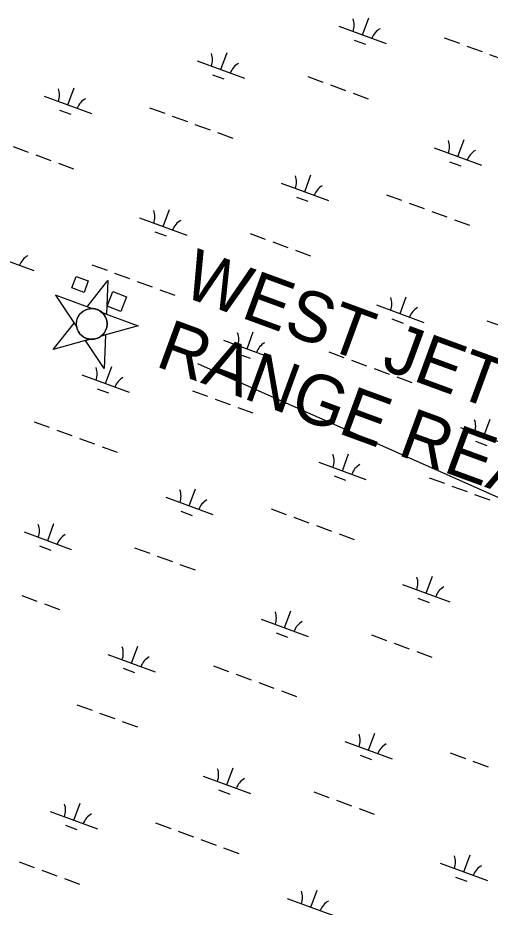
# Model space of a CAD drawing. Extents: x 3972907 to 3994831, y 172639 to 190852.
# Drawn here: x 3980783 to 3981252, y 185019 to 185903 of the extents above; entities that cross this region are included whole.
import ezdxf

# ---------------------------------------------------------------- set-up
doc = ezdxf.new("R2010")
doc.units = 0
for name, color, linetype in [('V-BLDG-OTLN', 7, 'Continuous'), ('V-CHAN-NAID', 7, 'Continuous'), ('V-RIVR-JETY', 7, 'Continuous'), ('V-RIVR-RANG', 7, 'Continuous'), ('V-WETL-SWMP', 7, 'Continuous')]:
    doc.layers.add(name, color=color, linetype=linetype)

msp = doc.modelspace()

# ---------------------------------------------------------------- linework, layer by layer
at = {"layer": 'V-BLDG-OTLN'}
for points in [[(3980848.54, 185630.29), (3980836.36, 185634.69), (3980840.47, 185646.04), (3980852.64, 185641.64)], [(3980871.33, 185616.44), (3980876.94, 185630.99), (3980890.54, 185625.75), (3980884.93, 185611.2)]]:
    msp.add_lwpolyline(points, close=True, dxfattribs=at)
at = {"layer": 'V-CHAN-NAID'}
for points in [[(3980855.84, 185614.14), (3980851.36, 185615.82), (3980872.2, 185641.99), (3980870.72, 185608.57), (3980866.23, 185610.25), (3980865.59, 185610.79), (3980864.71, 185611.44), (3980863.83, 185612.01), (3980862.93, 185612.5), (3980862.4, 185612.75), (3980861.69, 185613.06), (3980860.88, 185613.35), (3980860.23, 185613.56), (3980859.3, 185613.79), (3980858.62, 185613.92), (3980857.72, 185614.05), (3980856.93, 185614.11), (3980856.39, 185614.14)], [(3980855.84, 185614.14), (3980820.03, 185627.56), (3980841.12, 185595.65), (3980840.92, 185596.74), (3980840.82, 185597.64), (3980840.77, 185598.71), (3980840.8, 185599.79), (3980840.86, 185600.48), (3980840.97, 185601.3), (3980841.1, 185602.02), (3980841.29, 185602.8), (3980841.54, 185603.64), (3980841.8, 185604.38), (3980842.21, 185605.34), (3980842.57, 185606.07), (3980843.14, 185607.03), (3980843.69, 185607.85), (3980844.3, 185608.63), (3980844.9, 185609.31), (3980845.51, 185609.93), (3980846.16, 185610.51), (3980846.96, 185611.14), (3980847.69, 185611.66), (3980848.38, 185612.08), (3980849.05, 185612.44), (3980849.89, 185612.85), (3980850.55, 185613.12), (3980851.6, 185613.48), (3980852.32, 185613.68), (3980853.29, 185613.89), (3980854.27, 185614.04), (3980855.07, 185614.11)], [(3980866.23, 185610.25), (3980902.04, 185596.83), (3980865.18, 185586.63), (3980865.86, 185587.18), (3980866.64, 185587.87), (3980867.25, 185588.49), (3980867.93, 185589.29), (3980868.49, 185590.03), (3980868.96, 185590.73), (3980869.48, 185591.61), (3980869.84, 185592.32), (3980870.27, 185593.33), (3980870.62, 185594.31), (3980870.91, 185595.38), (3980871.09, 185596.25), (3980871.24, 185597.38), (3980871.31, 185598.5), (3980871.3, 185599.56), (3980871.24, 185600.35), (3980871.1, 185601.42), (3980870.9, 185602.41), (3980870.62, 185603.42), (3980870.29, 185604.36), (3980869.93, 185605.22), (3980869.43, 185606.22), (3980868.85, 185607.18), (3980868.27, 185608.02), (3980867.58, 185608.88), (3980867.02, 185609.49)], [(3980854.49, 185583.68), (3980817.63, 185573.49), (3980838.47, 185599.65), (3980841.12, 185595.65), (3980841.25, 185595.09), (3980841.58, 185593.98), (3980841.9, 185593.1), (3980842.33, 185592.15), (3980842.77, 185591.32), (3980843.25, 185590.53), (3980843.74, 185589.82), (3980844.35, 185589.05), (3980845, 185588.32), (3980845.7, 185587.64), (3980846.28, 185587.13), (3980846.96, 185586.6), (3980847.9, 185585.95), (3980848.57, 185585.55), (3980849.48, 185585.08), (3980850.18, 185584.77), (3980851.05, 185584.44), (3980851.86, 185584.18), (3980852.69, 185583.97), (3980853.64, 185583.79)], [(3980865.18, 185586.63), (3980869.8, 185587.91), (3980868.31, 185554.49), (3980849.87, 185582.4), (3980854.49, 185583.68), (3980855.36, 185583.61), (3980856.21, 185583.6), (3980857.38, 185583.66), (3980858.35, 185583.77), (3980859.41, 185583.98), (3980860.44, 185584.25), (3980861.38, 185584.56), (3980862.19, 185584.89), (3980863.08, 185585.32), (3980863.89, 185585.77), (3980864.67, 185586.27)]]:
    msp.add_lwpolyline(points, close=True, dxfattribs=at)
msp.add_circle((3980856.04, 185598.87), 15.27, dxfattribs=at)
at = {"layer": 'V-RIVR-JETY'}
msp.add_spline([(3980663.75, 188142.49), (3980923.3, 187897.84), (3981219.12, 187593.73), (3981381.55, 187411.23), (3981548.76, 187223.47), (3981745.95, 186997.4), (3981995.88, 186703.14), (3982287.95, 186350.33), (3982495.82, 186079.54), (3982762.84, 185654.69), (3982971.02, 185292.43), (3983111.24, 185037.47), (3983200.02, 184881.79), (3983229.93, 184826.38)], degree=3, dxfattribs=at)
at = {"layer": 'V-RIVR-RANG'}
msp.add_lwpolyline([(3980961.27, 185559.67), (3981961.68, 185114.26)], dxfattribs=at)
at = {"layer": 'V-WETL-SWMP'}
for p, q in [((3981125.21, 185886.27), (3981131.42, 185903.17)), ((3981101.75, 185894.9), (3981148.68, 185877.65)), ((3981206.52, 185883.42), (3981221.53, 185877.9)), ((3981116.92, 185881.1), (3981128.18, 185876.96)), ((3981229.04, 185875.14), (3981244.06, 185869.62)), ((3980984.44, 185851.79), (3980990.65, 185868.69)), ((3981251.57, 185866.86), (3981266.59, 185861.34)), ((3980960.97, 185860.41), (3981007.9, 185843.17)), ((3980976.14, 185846.62), (3980987.41, 185842.48)), ((3981070.85, 185844.76), (3981085.87, 185839.24)), ((3980832.28, 185816.72), (3980838.49, 185833.62)), ((3981093.38, 185836.48), (3981108.4, 185830.96)), ((3980808.82, 185825.35), (3980855.75, 185808.1)), ((3981115.9, 185828.2), (3981130.92, 185822.68)), ((3980913.58, 185813.87), (3980928.6, 185808.35)), ((3980823.99, 185811.55), (3980835.25, 185807.41)), ((3980936.11, 185805.59), (3980951.13, 185800.07)), ((3980958.64, 185797.31), (3980973.66, 185791.79)), ((3980981.16, 185789.03), (3980996.18, 185783.51)), ((3981219.99, 185765.21), (3981226.2, 185782.11)), ((3980777.92, 185775.21), (3980792.94, 185769.69)), ((3981196.52, 185773.84), (3981243.45, 185756.59)), ((3980800.45, 185766.93), (3980815.46, 185761.41)), ((3981211.69, 185760.04), (3981222.96, 185755.9)), ((3980822.97, 185758.65), (3980837.99, 185753.13)), ((3981067.83, 185730.15), (3981074.04, 185747.04)), ((3981044.36, 185738.77), (3981091.29, 185721.52)), ((3981059.54, 185724.98), (3981070.8, 185720.84)), ((3981149.13, 185727.29), (3981164.15, 185721.77)), ((3981171.66, 185719.02), (3981186.68, 185713.5)), ((3980927.05, 185695.66), (3980933.26, 185712.56)), ((3981194.19, 185710.74), (3981209.2, 185705.22)), ((3980903.59, 185704.29), (3980950.52, 185687.04)), ((3981216.71, 185702.46), (3981231.73, 185696.94)), ((3980918.76, 185690.49), (3980930.02, 185686.35)), ((3981013.47, 185688.64), (3981028.48, 185683.12)), ((3981035.99, 185680.36), (3981051.01, 185674.84)), ((3981058.52, 185672.08), (3981073.54, 185666.56)), ((3980751.43, 185669.22), (3980798.36, 185651.97)), ((3980856.2, 185657.74), (3980871.22, 185652.22)), ((3980878.73, 185649.46), (3980893.74, 185643.94)), ((3980901.25, 185641.19), (3980916.27, 185635.67)), ((3980923.78, 185632.91), (3980938.8, 185627.39)), ((3981139.14, 185617.71), (3981186.07, 185600.46)), ((3981162.6, 185609.09), (3981168.81, 185625.98)), ((3981154.31, 185603.92), (3981165.57, 185599.78)), ((3981249.01, 185602.06), (3981264.03, 185596.54)), ((3981010.44, 185574.02), (3981016.65, 185590.92)), ((3980986.98, 185582.65), (3981033.91, 185565.4)), ((3981002.15, 185568.85), (3981013.41, 185564.71)), ((3981091.75, 185571.17), (3981106.77, 185565.65)), ((3980869.67, 185539.54), (3980875.88, 185556.43)), ((3981114.27, 185562.89), (3981129.29, 185557.37)), ((3980846.21, 185548.16), (3980893.14, 185530.91)), ((3981136.8, 185554.61), (3981151.82, 185549.09)), ((3981159.33, 185546.33), (3981174.35, 185540.81)), ((3980861.38, 185534.37), (3980872.64, 185530.23)), ((3980956.08, 185532.51), (3980971.1, 185526.99)), ((3980978.61, 185524.23), (3980993.63, 185518.71)), ((3981001.14, 185515.95), (3981016.15, 185510.43)), ((3981245.99, 185487.45), (3981252.2, 185504.34)), ((3980798.82, 185501.62), (3980813.83, 185496.1)), ((3981222.53, 185496.07), (3981269.46, 185478.82)), ((3980821.34, 185493.34), (3980836.36, 185487.82)), ((3980843.87, 185485.06), (3980858.89, 185479.54)), ((3980866.4, 185476.78), (3980881.41, 185471.26)), ((3981237.7, 185482.27), (3981248.96, 185478.13)), ((3981105.22, 185452.96), (3981111.43, 185469.86)), ((3981081.75, 185461.59), (3981128.68, 185444.34)), ((3981096.92, 185447.79), (3981108.19, 185443.65)), ((3981191.63, 185445.94), (3981206.65, 185440.42)), ((3980953.06, 185417.9), (3980959.27, 185434.79)), ((3981214.16, 185437.66), (3981229.17, 185432.14)), ((3980929.6, 185426.52), (3980976.53, 185409.27)), ((3981236.68, 185429.38), (3981251.7, 185423.86)), ((3981034.36, 185415.04), (3981049.38, 185409.52)), ((3980944.77, 185412.72), (3980956.03, 185408.58)), ((3981056.89, 185406.76), (3981071.91, 185401.24)), ((3980812.29, 185383.41), (3980818.5, 185400.31)), ((3981079.42, 185398.48), (3981094.43, 185392.96)), ((3980788.82, 185392.04), (3980835.75, 185374.79)), ((3981101.94, 185390.2), (3981116.96, 185384.68)), ((3980803.99, 185378.24), (3980815.26, 185374.1)), ((3980898.7, 185376.39), (3980913.72, 185370.87)), ((3980921.23, 185368.11), (3980936.24, 185362.59)), ((3980943.75, 185359.83), (3980958.77, 185354.31)), ((3981188.61, 185331.32), (3981194.82, 185348.22)), ((3981165.14, 185339.94), (3981212.07, 185322.7)), ((3980786.49, 185328.93), (3980801.5, 185323.41)), ((3981180.31, 185326.15), (3981191.58, 185322.01)), ((3980809.01, 185320.65), (3980824.03, 185315.13)), ((3981047.83, 185296.84), (3981054.04, 185313.73)), ((3981024.37, 185305.46), (3981071.3, 185288.21)), ((3981039.54, 185291.67), (3981050.8, 185287.53)), ((3981134.25, 185289.81), (3981149.26, 185284.29)), ((3981156.77, 185281.53), (3981171.79, 185276.01)), ((3980895.68, 185261.77), (3980901.89, 185278.67)), ((3981179.3, 185273.25), (3981194.32, 185267.73)), ((3980872.21, 185270.39), (3980919.14, 185253.15)), ((3980887.38, 185256.6), (3980898.65, 185252.46)), ((3980976.98, 185258.92), (3980992, 185253.4)), ((3980999.51, 185250.64), (3981014.52, 185245.12)), ((3981022.03, 185242.36), (3981037.05, 185236.84)), ((3981044.56, 185234.08), (3981059.58, 185228.56)), ((3980841.31, 185220.26), (3980856.33, 185214.74)), ((3980863.84, 185211.98), (3980878.86, 185206.46)), ((3980886.37, 185203.7), (3980901.39, 185198.18)), ((3981131.22, 185175.19), (3981137.43, 185192.09)), ((3981107.76, 185183.82), (3981154.69, 185166.57)), ((3981122.93, 185170.02), (3981134.19, 185165.88)), ((3981212.53, 185172.34), (3981227.55, 185166.82)), ((3980990.45, 185140.71), (3980996.66, 185157.61)), ((3981235.05, 185164.06), (3981250.07, 185158.54)), ((3980966.98, 185149.34), (3981013.91, 185132.09)), ((3980982.16, 185135.54), (3980993.42, 185131.4)), ((3981076.86, 185133.68), (3981091.88, 185128.16)), ((3980838.29, 185105.64), (3980844.5, 185122.54)), ((3981099.39, 185125.4), (3981114.41, 185119.88)), ((3980814.83, 185114.27), (3980861.76, 185097.02)), ((3981121.92, 185117.12), (3981136.93, 185111.61)), ((3980830, 185100.47), (3980841.26, 185096.33)), ((3980919.6, 185102.79), (3980934.61, 185097.27)), ((3980942.12, 185094.51), (3980957.14, 185088.99)), ((3980964.65, 185086.23), (3980979.67, 185080.71)), ((3980987.18, 185077.95), (3981002.19, 185072.43)), ((3981226, 185054.14), (3981232.21, 185071.03)), ((3980783.93, 185064.13), (3980798.95, 185058.61)), ((3981202.53, 185062.76), (3981249.46, 185045.51)), ((3980806.46, 185055.85), (3980821.48, 185050.33)), ((3980828.98, 185047.57), (3980844, 185042.05)), ((3981217.7, 185048.96), (3981228.97, 185044.82)), ((3981073.84, 185019.07), (3981080.05, 185035.96)), ((3981050.37, 185027.69), (3981097.31, 185010.44))]:
    msp.add_line(p, q, dxfattribs=at)
for centre, start, end in [((3981099.37, 185896.02), 339.04728, 20.59094), ((3981151.22, 185876.97), 119.04728, 160.59093), ((3980958.59, 185861.54), 339.04728, 20.59094), ((3981010.45, 185842.48), 119.04728, 160.59093), ((3980806.44, 185826.47), 339.04728, 20.59094), ((3980858.29, 185807.42), 119.04728, 160.59093), ((3981194.14, 185774.97), 339.04728, 20.59094), ((3981245.99, 185755.91), 119.04728, 160.59093), ((3981041.98, 185739.9), 339.04728, 20.59094), ((3981093.84, 185720.84), 119.04728, 160.59093), ((3980901.21, 185705.42), 339.04728, 20.59094), ((3980953.06, 185686.36), 119.04728, 160.59093), ((3980800.9, 185651.29), 119.04728, 160.59093), ((3981136.76, 185618.84), 339.04728, 20.59094), ((3981188.61, 185599.78), 119.04728, 160.59093), ((3980984.6, 185583.77), 339.04728, 20.59094), ((3981036.45, 185564.72), 119.04728, 160.59093), ((3980843.83, 185549.29), 339.04728, 20.59094), ((3980895.68, 185530.23), 119.04728, 160.59093), ((3981220.15, 185497.2), 339.04728, 20.59094), ((3981079.37, 185462.72), 339.04728, 20.59094), ((3981131.23, 185443.66), 119.04728, 160.59093), ((3980927.22, 185427.65), 339.04728, 20.59094), ((3980979.07, 185408.59), 119.04728, 160.59093), ((3980786.44, 185393.16), 339.04728, 20.59094), ((3980838.29, 185374.11), 119.04728, 160.59093), ((3981162.76, 185341.07), 339.04728, 20.59094), ((3981214.62, 185322.01), 119.04728, 160.59093), ((3981021.99, 185306.59), 339.04728, 20.59094), ((3981073.84, 185287.53), 119.04728, 160.59093), ((3980869.83, 185271.52), 339.04728, 20.59094), ((3980921.68, 185252.46), 119.04728, 160.59093), ((3981105.38, 185184.95), 339.04728, 20.59094), ((3981157.23, 185165.89), 119.04728, 160.59093), ((3980964.61, 185150.46), 339.04728, 20.59094), ((3981016.46, 185131.41), 119.04728, 160.59093), ((3980812.45, 185115.4), 339.04728, 20.59094), ((3980864.3, 185096.34), 119.04728, 160.59093), ((3981200.15, 185063.89), 339.04728, 20.59094), ((3981252, 185044.83), 119.04728, 160.59093), ((3981048, 185028.82), 339.04728, 20.59094), ((3981099.85, 185009.76), 119.04728, 160.59093)]:
    msp.add_arc(centre, 17.62, start, end, dxfattribs=at)

# ---------------------------------------------------------------- texts
at = {"layer": 'V-CHAN-NAID'}
for s, p in [('WEST JETTY', (3980943.82, 185627.48)), ('RANGE REAR', (3980918.04, 185557.35))]:
    msp.add_text(s, height=50, rotation=339.86226, dxfattribs=at).set_placement(p)

doc.saveas('drawing.dxf')
